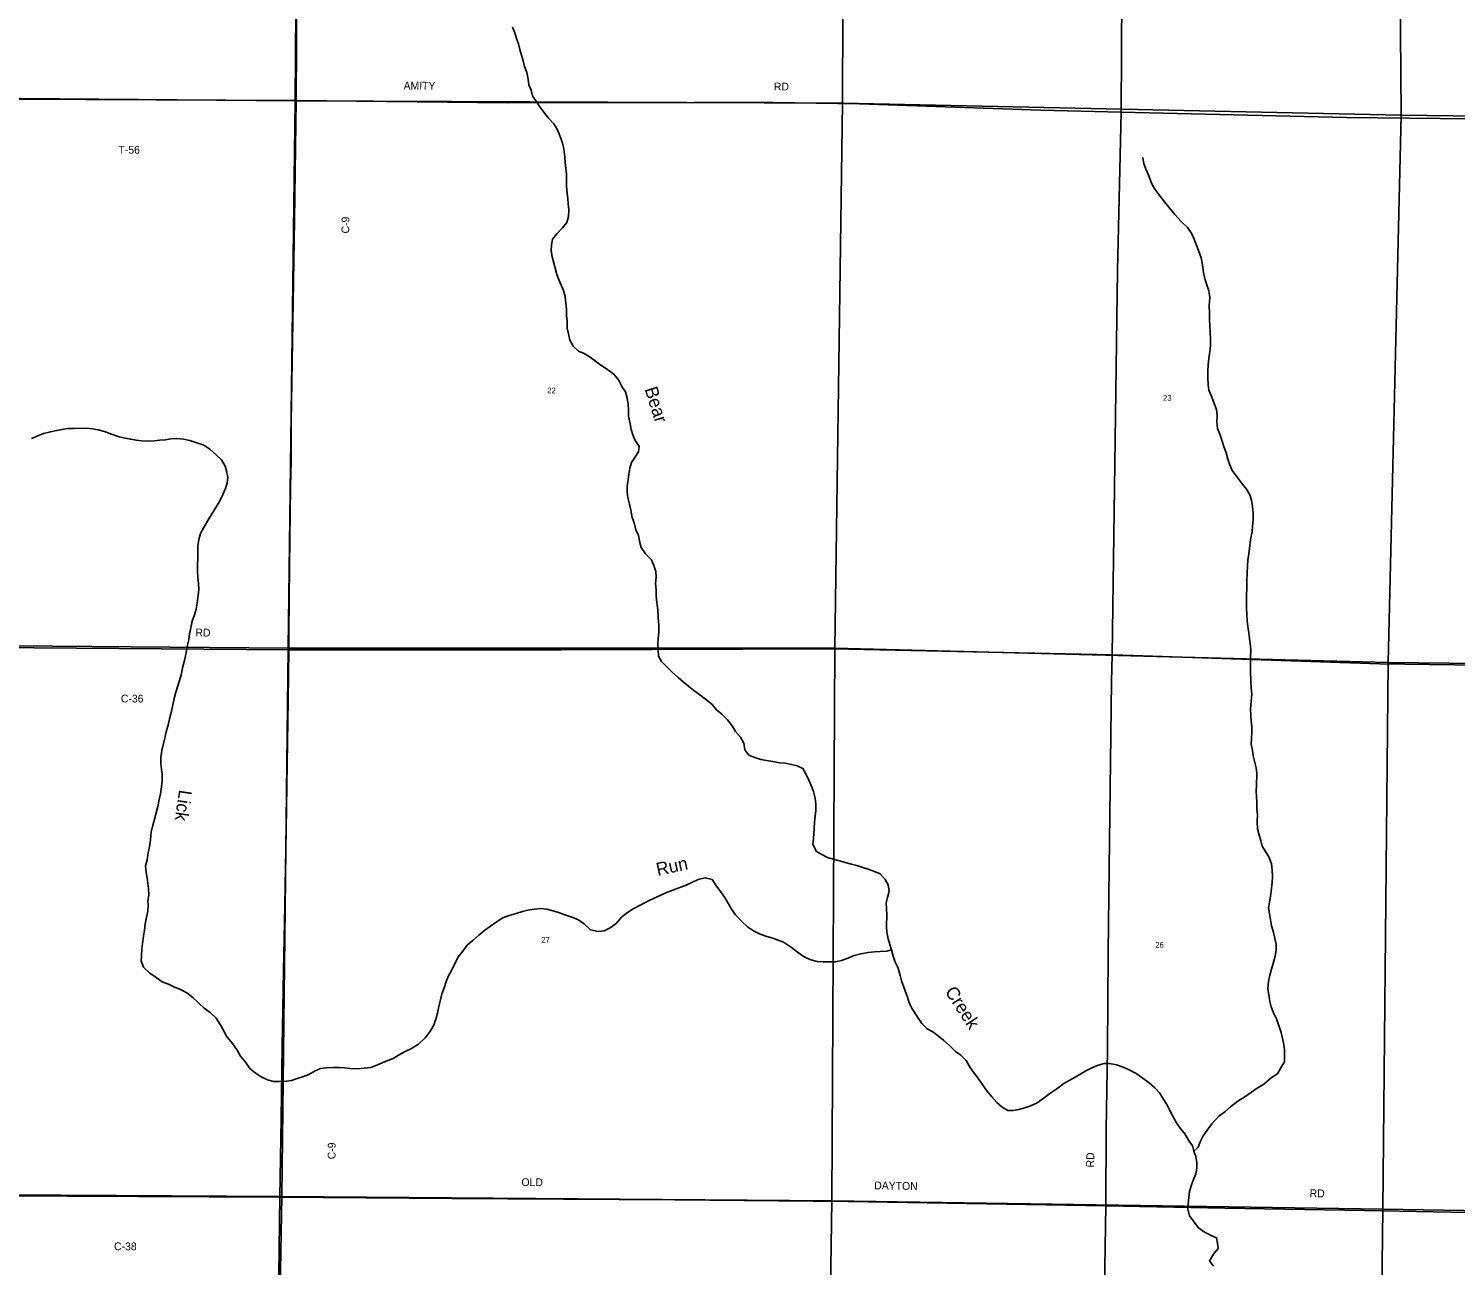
# Model space of a CAD drawing. Extents: x 1312308 to 1684953, y 460642 to 865172.
# Drawn here: x 1425482 to 1439210, y 646076 to 657978 of the extents above; entities that cross this region are included whole.
import ezdxf

# ---------------------------------------------------------------- set-up
doc = ezdxf.new("R2010")
doc.units = 0
for name, color, linetype in [('GM_X_County_Road', 7, 'Continuous'), ('GM_X_County_Road_Text', 7, 'Continuous'), ('GM_X_Minor_River', 7, 'Continuous'), ('GM_X_Minor_River_Text', 7, 'Continuous'), ('GM_X_Section', 7, 'Continuous'), ('GM_X_Section_Text', 7, 'Continuous'), ('GM_X_Township_Road', 7, 'Continuous'), ('GM_X_Township_Road_Text', 7, 'Continuous')]:
    doc.layers.add(name, color=color, linetype=linetype)

msp = doc.modelspace()

# ---------------------------------------------------------------- linework, layer by layer
at = {"layer": 'GM_X_County_Road'}
for points in [[(1435906, 651953), (1435935, 654019), (1435959, 655649), (1435993, 657172), (1436001, 658323), (1436006, 658824), (1436005, 659812), (1436004, 660609), (1436008, 662458), (1436043, 663301), (1436048, 664232), (1436042, 664641), (1436043, 665072), (1436048, 666772), (1436062, 667706)], [(1427987, 652001), (1427987, 652160), (1427993, 652809), (1428002, 653567), (1428007, 653820), (1428008, 654194), (1428019, 654773), (1428028, 655350), (1428042, 656134), (1428050, 656834), (1428056, 657285), (1428059, 657828), (1428063, 658421)], [(1422675, 652042), (1427987, 652001)], [(1427833, 642110), (1427878, 644997), (1427901, 646734), (1427911, 647487), (1427923, 648183), (1427936, 648907), (1427944, 649378), (1427947, 649539), (1427959, 650268), (1427970, 650905), (1427979, 651514), (1427987, 652001)], [(1427987, 652001), (1429299, 652001), (1430605, 652000), (1433225, 652008), (1435906, 651953), (1436011, 651949)], [(1435902, 651692), (1435906, 651953)], [(1436011, 651949), (1438483, 651865), (1442073, 651817), (1443846, 651791)], [(1435810, 643996), (1435820, 644690), (1435829, 645658), (1435846, 646649), (1435849, 647383), (1435863, 648146), (1435869, 649087), (1435880, 649901), (1435902, 651692)], [(1411320, 646883), (1412563, 646871), (1413651, 646859), (1414707, 646851), (1415585, 646844), (1417353, 646822), (1418330, 646813), (1419272, 646799), (1422342, 646771), (1423491, 646765), (1425173, 646747), (1427901, 646734)], [(1427901, 646734), (1429556, 646720), (1431700, 646707), (1433363, 646692), (1435846, 646649), (1436991, 646628), (1438334, 646604), (1439333, 646585), (1441120, 646548), (1442119, 646533), (1442887, 646530), (1443771, 646523)]]:
    msp.add_lwpolyline(points, dxfattribs=at)
at = {"layer": 'GM_X_Minor_River'}
for points in [[(1430645, 656688), (1430641, 656740), (1430635, 656795), (1430626, 656853), (1430610, 656904), (1430591, 656957), (1430569, 657010), (1430536, 657061), (1430483, 657117), (1430439, 657172), (1430402, 657224), (1430366, 657281), (1430331, 657332), (1430317, 657385), (1430296, 657436), (1430288, 657490), (1430275, 657555), (1430255, 657612), (1430241, 657669), (1430226, 657721), (1430210, 657778), (1430195, 657831), (1430177, 657884), (1430160, 657936), (1430138, 657993)], [(1432364, 651101), (1432333, 651158), (1432285, 651214), (1432250, 651267), (1432207, 651325), (1432153, 651381), (1432102, 651422), (1432059, 651474), (1432008, 651514), (1431941, 651568), (1431884, 651608), (1431833, 651647), (1431782, 651689), (1431731, 651735), (1431676, 651781), (1431627, 651832), (1431571, 651888), (1431542, 651939), (1431538, 652000), (1431535, 652056), (1431541, 652110), (1431545, 652168), (1431545, 652234), (1431539, 652315), (1431536, 652385), (1431526, 652456), (1431519, 652516), (1431519, 652577), (1431515, 652637), (1431519, 652699), (1431517, 652753), (1431498, 652812), (1431476, 652865), (1431419, 652923), (1431377, 652983), (1431362, 653033), (1431350, 653100), (1431326, 653153), (1431308, 653222), (1431289, 653272), (1431275, 653343), (1431263, 653402), (1431249, 653466), (1431242, 653517), (1431240, 653579), (1431250, 653637), (1431258, 653689), (1431267, 653749), (1431283, 653801), (1431315, 653852), (1431349, 653905), (1431358, 653957), (1431318, 654013), (1431295, 654069), (1431279, 654120), (1431271, 654175), (1431255, 654249), (1431253, 654310), (1431250, 654360), (1431240, 654423), (1431224, 654483), (1431189, 654535), (1431159, 654598), (1431112, 654653), (1431043, 654704), (1430988, 654740), (1430935, 654779), (1430884, 654815), (1430826, 654851), (1430773, 654875), (1430722, 654922), (1430691, 654980), (1430677, 655040), (1430665, 655095), (1430663, 655163), (1430656, 655218), (1430656, 655278), (1430650, 655334), (1430644, 655399), (1430628, 655457), (1430586, 655555), (1430566, 655612), (1430548, 655671), (1430535, 655721), (1430521, 655782), (1430511, 655841), (1430512, 655895), (1430522, 655951), (1430566, 656004), (1430618, 656060), (1430660, 656111), (1430676, 656171), (1430680, 656233), (1430675, 656290), (1430669, 656342), (1430664, 656392), (1430658, 656461), (1430658, 656513), (1430656, 656577), (1430650, 656632), (1430645, 656688)], [(1437259, 653191), (1437263, 653252), (1437263, 653316), (1437257, 653378), (1437249, 653439), (1437232, 653491), (1437200, 653547), (1437159, 653598), (1437109, 653662), (1437062, 653724), (1437036, 653785), (1437021, 653835), (1437003, 653896), (1436981, 653957), (1436966, 654008), (1436944, 654076), (1436922, 654131), (1436914, 654194), (1436919, 654252), (1436911, 654314), (1436889, 654369), (1436863, 654440), (1436838, 654497), (1436832, 654550), (1436828, 654616), (1436828, 654682), (1436830, 654741), (1436836, 654803), (1436846, 654869), (1436854, 654929), (1436854, 654993), (1436852, 655055), (1436847, 655118), (1436845, 655178), (1436845, 655242), (1436841, 655313), (1436846, 655391), (1436838, 655453), (1436817, 655512), (1436799, 655569), (1436787, 655632), (1436777, 655704), (1436763, 655771), (1436737, 655842), (1436716, 655899), (1436698, 655950), (1436673, 656002), (1436631, 656064), (1436572, 656122), (1436510, 656188), (1436452, 656260), (1436411, 656312), (1436355, 656380), (1436312, 656443), (1436284, 656496), (1436260, 656561), (1436231, 656624), (1436211, 656679), (1436203, 656730), (1436201, 656738)], [(1427135, 653118), (1427170, 653183), (1427206, 653244), (1427250, 653317), (1427284, 653369), (1427320, 653428), (1427352, 653493), (1427378, 653552), (1427392, 653608), (1427398, 653658), (1427391, 653711), (1427373, 653768), (1427338, 653827), (1427286, 653875), (1427227, 653931), (1427168, 653969), (1427102, 653991), (1427034, 654015), (1426974, 654027), (1426908, 654035), (1426851, 654031), (1426799, 654022), (1426746, 654018), (1426690, 654011), (1426633, 654009), (1426571, 654011), (1426517, 654017), (1426465, 654026), (1426411, 654036), (1426355, 654050), (1426281, 654076), (1426211, 654100), (1426152, 654116), (1426100, 654128), (1426033, 654134), (1425916, 654130), (1425858, 654129), (1425753, 654112), (1425692, 654098), (1425625, 654080), (1425570, 654058), (1425519, 654037), (1425509, 654034)], [(1428346, 647978), (1428290, 647970), (1428234, 647944), (1428179, 647915), (1428126, 647895), (1428067, 647875), (1428012, 647856), (1427962, 647848), (1427897, 647846), (1427837, 647845), (1427781, 647861), (1427719, 647891), (1427662, 647929), (1427611, 647971), (1427569, 648032), (1427522, 648090), (1427488, 648149), (1427443, 648211), (1427383, 648287), (1427357, 648340), (1427326, 648393), (1427286, 648457), (1427229, 648511), (1427172, 648552), (1427121, 648600), (1427061, 648654), (1427004, 648700), (1426938, 648734), (1426881, 648758), (1426827, 648782), (1426767, 648806), (1426710, 648848), (1426649, 648888), (1426588, 648946), (1426566, 649003), (1426568, 649055), (1426572, 649123), (1426577, 649175), (1426587, 649243), (1426597, 649303), (1426605, 649363), (1426615, 649427), (1426629, 649485), (1426631, 649535), (1426630, 649587), (1426638, 649639), (1426636, 649703), (1426626, 649780), (1426612, 649859), (1426608, 649921), (1426622, 649979), (1426634, 650045), (1426646, 650103), (1426654, 650173), (1426663, 650247), (1426674, 650299), (1426695, 650370), (1426724, 650492), (1426739, 650560), (1426750, 650614), (1426762, 650680), (1426768, 650738), (1426766, 650800), (1426760, 650850), (1426753, 650903), (1426755, 650965), (1426765, 651031), (1426781, 651099), (1426793, 651153), (1426807, 651210), (1426825, 651276), (1426839, 651336), (1426855, 651396), (1426869, 651469), (1426883, 651533), (1426899, 651591), (1426915, 651645), (1426933, 651704), (1426949, 651760), (1426965, 651838), (1426983, 651898), (1426997, 651972), (1427009, 652031), (1427023, 652095), (1427031, 652153), (1427043, 652213), (1427057, 652277), (1427077, 652337), (1427093, 652390), (1427105, 652448), (1427113, 652522), (1427119, 652584), (1427117, 652637), (1427111, 652701), (1427108, 652753), (1427108, 652816), (1427112, 652882), (1427110, 652934), (1427110, 652996), (1427120, 653062), (1427135, 653118)], [(1436692, 647177), (1436735, 647214), (1436759, 647271), (1436783, 647323), (1436821, 647378), (1436867, 647439), (1436935, 647511), (1436991, 647555), (1437047, 647602), (1437115, 647658), (1437183, 647700), (1437247, 647744), (1437302, 647781), (1437368, 647819), (1437436, 647881), (1437498, 647921), (1437534, 647985), (1437564, 648036), (1437567, 648092), (1437565, 648150), (1437559, 648203), (1437546, 648259), (1437532, 648316), (1437488, 648450), (1437457, 648513), (1437437, 648564), (1437426, 648616), (1437416, 648683), (1437406, 648739), (1437412, 648808), (1437426, 648869), (1437442, 648927), (1437460, 648995), (1437476, 649053), (1437486, 649108), (1437484, 649165), (1437473, 649225), (1437457, 649292), (1437439, 649343), (1437431, 649403), (1437420, 649464), (1437412, 649516), (1437424, 649592), (1437434, 649646), (1437442, 649706), (1437446, 649762), (1437449, 649820), (1437447, 649879), (1437439, 649941), (1437417, 650000), (1437388, 650051), (1437352, 650110), (1437337, 650163), (1437319, 650228), (1437306, 650279), (1437304, 650345), (1437305, 650413), (1437300, 650467), (1437298, 650536), (1437296, 650586), (1437293, 650642), (1437297, 650694), (1437301, 650811), (1437294, 650863), (1437278, 650928), (1437264, 650981), (1437257, 651035), (1437245, 651090), (1437249, 651148), (1437252, 651204), (1437252, 651260), (1437246, 651314), (1437241, 651367), (1437239, 651433), (1437246, 651507), (1437250, 651569), (1437246, 651638), (1437243, 651692), (1437239, 651805), (1437238, 651859), (1437240, 651927), (1437241, 652001), (1437236, 652060), (1437230, 652110), (1437224, 652164), (1437213, 652223), (1437207, 652279), (1437203, 652332), (1437201, 652408), (1437201, 652468), (1437200, 652523), (1437203, 652595), (1437203, 652659), (1437205, 652739), (1437209, 652809), (1437213, 652862), (1437221, 652926), (1437231, 653000), (1437239, 653062), (1437254, 653139), (1437259, 653191)], [(1436365, 647735), (1436314, 647787), (1436263, 647832), (1436204, 647878), (1436139, 647924), (1436072, 647959), (1436014, 647983), (1435948, 648007), (1435882, 648019), (1435830, 648020), (1435773, 648004), (1435718, 647981), (1435661, 647953), (1435607, 647921), (1435552, 647888), (1435441, 647827), (1435375, 647775), (1435308, 647731), (1435254, 647690), (1435186, 647640), (1435133, 647616), (1435076, 647595), (1435011, 647577), (1434954, 647567), (1434904, 647566), (1434849, 647598), (1434798, 647644), (1434749, 647698), (1434701, 647757), (1434658, 647821), (1434616, 647880), (1434571, 647938), (1434535, 647989), (1434502, 648048), (1434451, 648100), (1434400, 648134), (1434342, 648192), (1434289, 648242), (1434234, 648285), (1434181, 648325), (1434127, 648353), (1434076, 648405), (1434030, 648472), (1433984, 648544), (1433954, 648603), (1433937, 648656), (1433902, 648755), (1433882, 648814), (1433867, 648867), (1433847, 648938), (1433819, 648995), (1433802, 649052), (1433784, 649112), (1433768, 649165), (1433753, 649220), (1433739, 649284), (1433735, 649337), (1433738, 649453), (1433736, 649507), (1433734, 649564), (1433745, 649616), (1433761, 649679), (1433751, 649738), (1433722, 649789), (1433674, 649843), (1433622, 649866), (1433560, 649888), (1433509, 649906), (1433451, 649926), (1433399, 649939), (1433339, 649955), (1433283, 649971), (1433223, 649985), (1433169, 650002), (1433114, 650030), (1433062, 650060), (1433028, 650127), (1433034, 650181), (1433037, 650231), (1433041, 650281), (1433045, 650340), (1433051, 650398), (1433058, 650454), (1433058, 650514), (1433050, 650572), (1433034, 650637), (1433011, 650694), (1432989, 650747), (1432964, 650800), (1432932, 650857), (1432878, 650883), (1432822, 650898), (1432762, 650908), (1432706, 650914), (1432642, 650926), (1432582, 650936), (1432526, 650946), (1432470, 650965), (1432412, 650987), (1432372, 651039), (1432364, 651101)], [(1433784, 649112), (1433741, 649100), (1433675, 649098), (1433620, 649093), (1433558, 649087), (1433489, 649075), (1433424, 649057), (1433357, 649031), (1433304, 649012), (1433245, 648998), (1433195, 648996), (1433126, 648998), (1433068, 649002), (1433008, 649017), (1432943, 649046), (1432880, 649090), (1432821, 649136), (1432746, 649186), (1432644, 649225), (1432586, 649241), (1432521, 649265), (1432457, 649295), (1432400, 649335), (1432345, 649385), (1432283, 649449), (1432246, 649504), (1432217, 649555), (1432185, 649609), (1432141, 649672), (1432100, 649726), (1432058, 649789), (1431992, 649807), (1431925, 649791), (1431870, 649765), (1431808, 649735), (1431747, 649712), (1431682, 649686), (1431621, 649664), (1431566, 649639), (1431496, 649607), (1431445, 649583), (1431372, 649547), (1431298, 649507), (1431243, 649473), (1431191, 649430), (1431135, 649367), (1431079, 649325), (1431020, 649295), (1430963, 649288), (1430887, 649307), (1430827, 649363), (1430765, 649405), (1430708, 649429), (1430642, 649451), (1430590, 649468), (1430538, 649484), (1430467, 649504), (1430408, 649510), (1430348, 649504), (1430285, 649494), (1430234, 649483), (1430173, 649463), (1430106, 649445), (1430045, 649421), (1429990, 649386), (1429926, 649342), (1429871, 649302), (1429813, 649253), (1429755, 649203), (1429703, 649158), (1429659, 649101), (1429619, 649050), (1429587, 648987), (1429551, 648914), (1429519, 648858), (1429499, 648807), (1429479, 648747), (1429459, 648690), (1429441, 648620), (1429429, 648568), (1429415, 648504), (1429401, 648446), (1429381, 648387), (1429343, 648324), (1429299, 648265), (1429233, 648206), (1429165, 648164), (1429106, 648134), (1429042, 648098), (1428991, 648069), (1428938, 648047), (1428885, 648026), (1428832, 648002), (1428775, 647981), (1428712, 647973), (1428646, 647967), (1428575, 647971), (1428521, 647979), (1428471, 647981), (1428411, 647981), (1428346, 647978)], [(1436883, 646069), (1436844, 646122), (1436881, 646183), (1436927, 646240), (1436922, 646290), (1436912, 646343), (1436860, 646363), (1436795, 646397), (1436737, 646439), (1436695, 646492), (1436652, 646552), (1436634, 646618), (1436640, 646670), (1436646, 646730), (1436651, 646787), (1436672, 646852), (1436689, 646904), (1436711, 646959), (1436723, 647011), (1436723, 647068), (1436712, 647124), (1436692, 647177), (1436679, 647227), (1436643, 647281), (1436606, 647342), (1436562, 647396), (1436525, 647449), (1436491, 647514), (1436460, 647575), (1436434, 647626), (1436399, 647680), (1436365, 647735)]]:
    msp.add_lwpolyline(points, dxfattribs=at)
at = {"layer": 'GM_X_Section'}
for points in [[(1428085, 662539), (1428048, 657284), (1422753, 657328), (1422795, 662601)], [(1428085, 662539), (1433331, 662515), (1433314, 657259), (1428048, 657284)], [(1438647, 662357), (1438689, 657144), (1433314, 657259), (1433331, 662515)], [(1438647, 662357), (1444022, 662322), (1443918, 657174), (1443914, 657078), (1438689, 657144)], [(1422753, 657328), (1428048, 657284), (1427979, 652016), (1422686, 652061)], [(1433314, 657259), (1433239, 652017), (1427979, 652016), (1428048, 657284)], [(1438689, 657144), (1438564, 651877), (1433239, 652017), (1433314, 657259)], [(1438689, 657144), (1443914, 657078), (1443841, 652140), (1443841, 651820), (1438564, 651877)], [(1427979, 652016), (1427920, 646739), (1422607, 646771), (1422686, 652061)], [(1427979, 652016), (1433239, 652017), (1433209, 646698), (1427920, 646739)], [(1433239, 652017), (1438564, 651877), (1438511, 646616), (1433209, 646698)], [(1438564, 651877), (1443841, 651820), (1443766, 646532), (1438511, 646616)], [(1422607, 646771), (1427920, 646739), (1427821, 641423), (1427620, 641429), (1422563, 641480)], [(1427920, 646739), (1433209, 646698), (1433131, 641381), (1432891, 641384), (1427821, 641423)], [(1433209, 646698), (1438511, 646616), (1438449, 641321), (1438421, 641319), (1433131, 641381)], [(1438511, 646616), (1443766, 646532), (1443676, 641259), (1438449, 641321)]]:
    msp.add_lwpolyline(points, close=True, dxfattribs=at)
at = {"layer": 'GM_X_Township_Road'}
msp.add_lwpolyline([(1411381, 657447), (1413488, 657427), (1415071, 657420), (1415952, 657413), (1417492, 657404), (1418688, 657381), (1419242, 657371), (1420247, 657351), (1421339, 657334), (1422749, 657312), (1424000, 657305), (1428056, 657285), (1430092, 657264), (1431889, 657267), (1432642, 657267), (1433478, 657255), (1435222, 657193), (1435993, 657172), (1438163, 657123), (1439667, 657105), (1441263, 657089), (1443921, 657079)], dxfattribs=at)

# ---------------------------------------------------------------- texts
at = {"layer": 'GM_X_County_Road_Text'}
for s, rotation, p in [('C-9', 89.5419, (1428567, 656006)), ('RD', 359.5064, (1427087, 652129)), ('C-36', 359.6571, (1426370, 651494)), ('C-9', 89.1088, (1428434, 647097)), ('RD', 89.0118, (1435733, 647019)), ('OLD', 359.6651, (1430224, 646840)), ('DAYTON', 359.0234, (1433618, 646809)), ('RD', 359.0128, (1437807, 646734)), ('C-38', 359.6558, (1426304, 646223))]:
    msp.add_text(s, height=75, rotation=rotation, dxfattribs=at).set_placement(p)
at = {"layer": 'GM_X_Minor_River_Text'}
for s, rotation, p in [('Bear', 287.5377, (1431408, 654510)), ('Lick', 261.5901, (1426931, 650658)), ('Run', 12.2751, (1431535, 649824)), ('Creek', 303.0874, (1434294, 648711))]:
    msp.add_text(s, height=125, rotation=rotation, dxfattribs=at).set_placement(p)
at = {"layer": 'GM_X_Section_Text'}
for s, p in [('22', (1430472, 654468)), ('23', (1436397, 654396)), ('27', (1430415, 649182)), ('26', (1436322, 649133))]:
    msp.add_text(s, height=55.3, rotation=0, dxfattribs=at).set_placement(p)
at = {"layer": 'GM_X_Township_Road_Text'}
for s, rotation, p in [('AMITY', 359.5804, (1429090, 657392)), ('RD', 359.5064, (1432653, 657383)), ('T-56', 0, (1426347, 656774))]:
    msp.add_text(s, height=75, rotation=rotation, dxfattribs=at).set_placement(p)

doc.saveas('drawing.dxf')
